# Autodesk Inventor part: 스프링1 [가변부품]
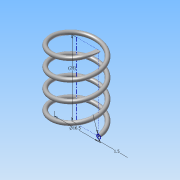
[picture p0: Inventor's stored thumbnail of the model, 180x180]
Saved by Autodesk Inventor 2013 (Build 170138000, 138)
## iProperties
Created: 2015-08
Part Number: 스프링1 [가변부품]
Material: 강철, 연강
Document SubType Name: Modeling
Designer: Administrator
Mass: 2.84334 g
Surface Area: 9.78838 cm^2
Volume: 0.361748 cm^3
Density: 7.86 g/cm^3
Author: Administrator
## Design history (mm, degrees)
sketch "스케치1"
  geometry: L1 (0, 0)-(8.25, 0); L2 (8.25, 0)-(8.25, 28); L3 (8.25, 28)-(0, 28); L4 (0, 28)-(0, 0); C1 r 0.75 at (8.25, 0)
  constraints: 8 end point, 2 parallel, 1 centre point, 1 coincident, 1 horizontal, 1 perpendicular
  dimensions: "d0" = 1.5 diameter of C1; "d2" = 16.5 diameter of L2 L4; "d3" = 28 distance of L3.end L1.start (derived)
feature "코일1" pitch "d4" = 10; turns "d6" = 4; dims "d5" = 28 (= d3), "d7" = 0, angle "d8" = 90 deg, angle "d9" = 90 deg, "d10" = 0, "d11" = 0
sketch "스케치2"
  geometry: L1 (-9, 0)-(-7.5, 0) reference; 1 further point
  constraints: 1 horizontal alignment
extrude "돌출1" cut sketch "스케치2" distance "d12" = 10; taper "d13" = 0 deg
node "작업 평면1"
sketch "스케치3"
  geometry: L1 (1.5, 0)-(0, 0) reference; 1 further point
  constraints: 1 horizontal alignment
extrude "돌출2" cut sketch "스케치3" distance "d14" = 10; taper "d15" = 0 deg
node "솔리드1"
node "절단 모서리 투영1"
node "절단 모서리 투영2"
